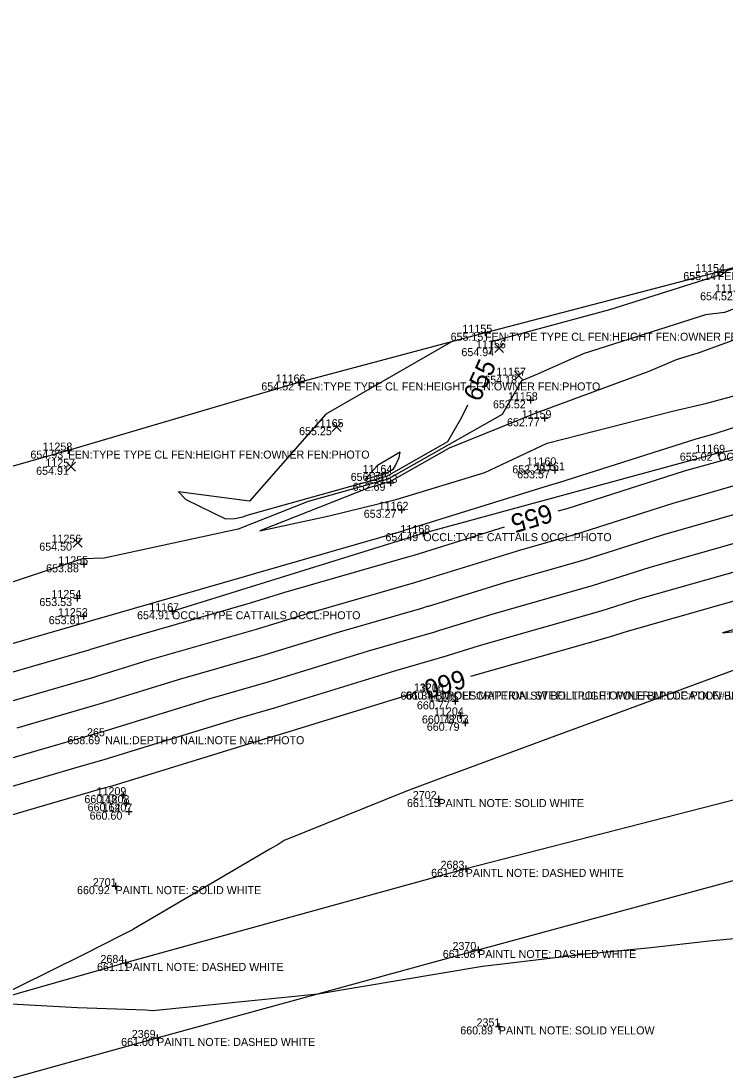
# Model space of a CAD drawing. Extents: x 2129350 to 2137777, y 657588 to 659885.
# Drawn here: x 2130064.8 to 2130170.4, y 657889 to 658046.3 of the extents above; entities that cross this region are included whole.
import ezdxf

# ---------------------------------------------------------------- set-up
doc = ezdxf.new("R2010")
doc.units = 0
for name, color, linetype in [('DT_X_Contour_Major', 7, 'Continuous'), ('DT_X_Contour_Minor', 7, 'Continuous'), ('DT_X_TIN_Hull', 7, 'Continuous'), ('PV_X_COP', 7, 'Continuous'), ('SV_X_Occupation_Line', 7, 'Continuous'), ('SV_X_Random_Point', 7, 'Continuous'), ('SV_X_Shot_Marker', 7, 'Continuous'), ('SV_X_Text_Comment', 7, 'Continuous'), ('SV_X_Text_Elevation', 7, 'Continuous'), ('SV_X_Text_Name', 7, 'Continuous')]:
    doc.layers.add(name, color=color, linetype=linetype)

msp = doc.modelspace()

# ---------------------------------------------------------------- linework, layer by layer
at = {"layer": 'DT_X_Contour_Major'}
for points in [[(2130135.26, 657996.37), (2130135.53, 657998.3), (2130153.1, 658003), (2130169.13, 658008.07), (2130169.76, 658008.15), (2130170.68, 658008.86), (2130207.13, 658019.25)], [(2130145.36, 657972.83), (2130146.73, 657973.21), (2130164.33, 657978.81), (2130170.25, 657980.49), (2130170.87, 657980.67), (2130178.19, 657983.07), (2130184.13, 657984.71), (2130202.48, 657988.72), (2130206.5, 657989.34), (2130213.65, 657991.31), (2130224.32, 657996.57), (2130224.46, 657996.61), (2130241.1, 658000.69)], [(2130129.37, 657998.2), (2130110.5, 657987.31), (2130099.06, 657974.3), (2130088.39, 657975.7), (2130089.52, 657974.52), (2130095.46, 657971.63), (2130096.84, 657971.67), (2130098.08, 657971.94), (2130098.72, 657972.19), (2130119.66, 657978.02), (2130119.68, 657978.03), (2130128.83, 657983.21), (2130130.91, 657986.87), (2130131.81, 657988.74)], [(2130228.35, 657975.26), (2130228.33, 657975.26), (2130226.38, 657974.3), (2130205.36, 657968.48), (2130204.63, 657968.37), (2130201.34, 657967.65), (2130180.5, 657961.87), (2130179.2, 657961.44), (2130176.95, 657960.8), (2130155.69, 657954.76), (2130153.02, 657953.91), (2130132.19, 657948.01)], [(2130041.36, 657942.26), (2130051.69, 657945.25), (2130055.75, 657946.43), (2130075.01, 657952), (2130075.27, 657952.08), (2130079.61, 657953.41), (2130099.21, 657959.04), (2130104.19, 657960.57), (2130123.15, 657966.03), (2130123.55, 657966.15), (2130123.75, 657966.21), (2130137.31, 657970.42)], [(2130124.14, 657945.59), (2130103.64, 657939.28), (2130101.6, 657938.7), (2130079.71, 657931.95), (2130078.4, 657931.57), (2130076.87, 657931.13), (2130054.42, 657924.58), (2130053.07, 657924.19), (2130030.38, 657917.57), (2130030.36, 657917.56), (2130030.36, 657917.56), (2130029.26, 657917.28), (2130028.32, 657916.99)]]:
    msp.add_lwpolyline(points, dxfattribs=at)
at = {"layer": 'DT_X_Contour_Minor'}
for points in [[(2130173.21, 658003.68), (2130170.31, 658002.6), (2130167.47, 658002.21), (2130149.09, 657996.4), (2130142.25, 657993.33), (2130139.84, 657992.31), (2130136.98, 657987.29), (2130119.9, 657977.61), (2130119.85, 657977.59), (2130107.84, 657974.25), (2130097.34, 657970.1), (2130077.27, 657965.74), (2130073.99, 657965.64), (2130053.45, 657958.82)], [(2130175.12, 657999.7), (2130166.23, 657996.41), (2130165.8, 657996.35), (2130163.04, 657995.48), (2130162.01, 657995.02), (2130158.96, 657993.72), (2130142.54, 657987.69), (2130142.51, 657987.68), (2130129.03, 657982.24), (2130120.12, 657977.19), (2130120.05, 657977.16), (2130116.96, 657976.3), (2130100.61, 657969.84), (2130111, 657972.08), (2130121, 657974.54), (2130121.03, 657974.55), (2130121.19, 657974.59), (2130134.34, 657978.58), (2130143.72, 657982.96), (2130143.73, 657982.96), (2130162.5, 657987.79), (2130167.67, 657988.97), (2130177.09, 657991.53)], [(2130051.53, 657949.49), (2130074.34, 657956.09), (2130074.38, 657956.1), (2130075.21, 657956.35), (2130098.33, 657962.99), (2130099.99, 657963.5), (2130122.27, 657969.91), (2130122.44, 657969.97), (2130122.67, 657970.03), (2130143.89, 657976.62), (2130145.47, 657977.07), (2130166.06, 657983.62), (2130168.9, 657984.43), (2130169.21, 657984.52), (2130177.73, 657987.3)], [(2130119.46, 657978.45), (2130120.68, 657979.14), (2130120.96, 657979.63), (2130121.53, 657980.81), (2130121.64, 657981.62), (2130118.24, 657979.63), (2130116.42, 657977.6), (2130119.46, 657978.45), (2130119.46, 657978.45)], [(2130059.97, 657943.37), (2130075.69, 657947.91), (2130076.16, 657948.05), (2130084.01, 657950.47), (2130100.1, 657955.09), (2130108.39, 657957.64), (2130124.03, 657962.14), (2130124.67, 657962.34), (2130124.82, 657962.38), (2130139.74, 657967.01), (2130147.99, 657969.35), (2130162.6, 657974), (2130171.59, 657976.56)], [(2130064.2, 657940.31), (2130076.37, 657943.83), (2130077.05, 657944.03), (2130088.4, 657947.53), (2130100.98, 657951.14), (2130112.58, 657954.71), (2130124.92, 657958.26), (2130125.78, 657958.52), (2130125.9, 657958.56), (2130137.66, 657962.21), (2130149.24, 657965.49), (2130160.87, 657969.19), (2130172.93, 657972.62)], [(2130053.33, 657932.85), (2130068.42, 657937.25), (2130077.05, 657939.74), (2130077.93, 657940), (2130092.8, 657944.58), (2130101.87, 657947.19), (2130116.78, 657951.77), (2130125.8, 657954.37), (2130126.89, 657954.7), (2130126.98, 657954.73), (2130135.59, 657957.41), (2130150.5, 657961.63), (2130159.15, 657964.38), (2130174.27, 657968.68)], [(2130175.61, 657964.74), (2130157.42, 657959.57), (2130151.76, 657957.77), (2130133.51, 657952.6), (2130128.06, 657950.91), (2130128, 657950.89), (2130126.68, 657950.48), (2130120.98, 657948.84), (2130102.75, 657943.23), (2130097.2, 657941.64), (2130078.82, 657935.98), (2130077.72, 657935.66), (2130072.65, 657934.19), (2130053.87, 657928.71)], [(2130178.29, 657956.87), (2130170.03, 657954.52), (2130173.15, 657954.87)], [(2130180.24, 657952.07), (2130164.98, 657946.44), (2130154.81, 657942.7), (2130144.05, 657938.73), (2130129.45, 657933.36), (2130128.71, 657933.09), (2130128.6, 657933.05), (2130122.61, 657930.82), (2130104.28, 657923.38), (2130103.38, 657922.81), (2130102.1, 657922.11), (2130081.64, 657910.1), (2130081.59, 657910.07), (2130079.93, 657909.23), (2130074.09, 657906.26), (2130059.6, 657899.1), (2130073.25, 657898.34), (2130083.44, 657898), (2130084.56, 657897.91), (2130109.32, 657900.4), (2130109.32, 657900.4), (2130109.32, 657900.4), (2130134.02, 657904.56), (2130134.05, 657904.56), (2130149.13, 657906.36), (2130159.24, 657907.35), (2130167.99, 657908.35), (2130184.51, 657909.89)]]:
    msp.add_lwpolyline(points, dxfattribs=at)
at = {"layer": 'DT_X_TIN_Hull'}
msp.add_lwpolyline([(2130245.51, 658030.02), (2130169.29, 658008.63), (2130134.39, 657999.54), (2130106.47, 657992.08), (2130071.87, 657981.87), (2130012.21, 657964.92), (2129966.74, 657952.64), (2129918.6, 657939.53), (2129870.14, 657926.57), (2129855.49, 657922.41), (2129844.49, 657920.37), (2129839.1, 657899.07), (2129833.96, 657888.24), (2129831.53, 657881.88), (2129820.99, 657877.99), (2129803, 657870.9), (2129789.34, 657849.46), (2129788.09, 657848.81), (2129788.13, 657848.34), (2129789.97, 657847.16), (2129789.65, 657836.99), (2129741.65, 657823.5), (2129717.53, 657816.91), (2129695.67, 657810.93)], dxfattribs=at)
at = {"layer": 'PV_X_COP'}
for points in [[(2130756.8, 658090.85), (2130709.64, 658077.1), (2130660.65, 658064.17), (2130611.76, 658050.53), (2130564.1, 658038.01), (2130516.21, 658024.74), (2130467.7, 658011.29), (2130419.56, 657997.56), (2130371.3, 657984.1), (2130323.4, 657971.71), (2130275.02, 657958.65), (2130226.86, 657945.08), (2130178.24, 657931.16), (2130131.49, 657919.16), (2130080.47, 657905.05), (2130033.67, 657891.71)], [(2130037.09, 657880.45), (2130085.21, 657893.8), (2130133.36, 657906.99), (2130181.98, 657920.22), (2130229.94, 657933.91), (2130277.86, 657946.56), (2130326.08, 657959.87), (2130374.09, 657973.32), (2130422.71, 657986.65), (2130470.82, 658000.08), (2130519.45, 658012.91), (2130567.41, 658026.23), (2130615.61, 658039.6), (2130663.49, 658052.2), (2130712.28, 658065.72), (2130760.53, 658079.19)]]:
    msp.add_lwpolyline(points, dxfattribs=at)
at = {"layer": 'SV_X_Occupation_Line'}
msp.add_lwpolyline([(2130087.44, 657957.79), (2130125.12, 657969.49), (2130169.35, 657981.55), (2130211.47, 657989.69), (2130262.21, 658002.55), (2130300.39, 658019.48), (2130344.82, 658026.09), (2130388.98, 658037.78), (2130435.6, 658050.49), (2130554.92, 658087.06), (2130644.25, 658113.16), (2130752.81, 658143.9), (2130803.09, 658157.94), (2130847.96, 658175.12), (2130903.78, 658194.81)], dxfattribs=at)
at = {"layer": 'SV_X_Random_Point'}
for p, q in [((2130135.85, 657996.56), (2130137.18, 657997.89)), ((2130135.85, 657997.89), (2130137.18, 657996.56)), ((2130138.8, 657992.43), (2130140.13, 657993.76)), ((2130138.8, 657993.76), (2130140.13, 657992.43)), ((2130111.46, 657984.72), (2130112.79, 657986.05)), ((2130111.46, 657986.05), (2130112.79, 657984.72)), ((2130071.63, 657978.78), (2130072.96, 657980.11)), ((2130071.63, 657980.11), (2130072.96, 657978.78)), ((2130072.62, 657967.39), (2130073.95, 657968.73)), ((2130072.62, 657968.73), (2130073.95, 657967.39))]:
    msp.add_line(p, q, dxfattribs=at)
at = {"layer": 'SV_X_Shot_Marker'}
for p, q in [((2130169.29, 658009.13), (2130169.29, 658008.13)), ((2130168.79, 658008.63), (2130169.79, 658008.63)), ((2130169.29, 658008.63), (2130169.29, 658008.63)), ((2130133.89, 657999.54), (2130134.89, 657999.54)), ((2130134.39, 658000.04), (2130134.39, 657999.04)), ((2130134.39, 657999.54), (2130134.39, 657999.54)), ((2130105.98, 657992.08), (2130106.98, 657992.08)), ((2130106.48, 657992.58), (2130106.48, 657991.58)), ((2130106.48, 657992.08), (2130106.48, 657992.08)), ((2130140.73, 657989.41), (2130141.73, 657989.41)), ((2130141.23, 657989.91), (2130141.23, 657988.91)), ((2130141.23, 657989.41), (2130141.23, 657989.41)), ((2130143.29, 657987.22), (2130143.29, 657986.22)), ((2130142.79, 657986.72), (2130143.79, 657986.72)), ((2130143.29, 657986.72), (2130143.29, 657986.72)), ((2130071.87, 657982.37), (2130071.87, 657981.37)), ((2130071.37, 657981.87), (2130072.37, 657981.87)), ((2130071.87, 657981.87), (2130071.87, 657981.87)), ((2130168.85, 657981.55), (2130169.85, 657981.55)), ((2130169.35, 657982.05), (2130169.35, 657981.05)), ((2130169.35, 657981.55), (2130169.35, 657981.55)), ((2130119.43, 657979.02), (2130119.43, 657978.02)), ((2130143.63, 657979.65), (2130144.63, 657979.65)), ((2130144.13, 657980.15), (2130144.13, 657979.15)), ((2130144.13, 657979.65), (2130144.13, 657979.65)), ((2130144.87, 657979.41), (2130144.87, 657978.41)), ((2130118.93, 657978.52), (2130119.93, 657978.52)), ((2130119.43, 657978.52), (2130119.43, 657978.52)), ((2130120.19, 657977.54), (2130120.19, 657976.54)), ((2130144.37, 657978.91), (2130145.37, 657978.91)), ((2130144.87, 657978.91), (2130144.87, 657978.91)), ((2130119.69, 657977.04), (2130120.69, 657977.04)), ((2130120.19, 657977.04), (2130120.19, 657977.04)), ((2130121.34, 657972.99), (2130122.34, 657972.99)), ((2130121.84, 657973.49), (2130121.84, 657972.49)), ((2130121.84, 657972.99), (2130121.84, 657972.99)), ((2130124.62, 657969.49), (2130125.62, 657969.49)), ((2130125.12, 657969.99), (2130125.12, 657968.99)), ((2130125.12, 657969.49), (2130125.12, 657969.49)), ((2130073.73, 657964.82), (2130074.73, 657964.82)), ((2130074.23, 657965.32), (2130074.23, 657964.32)), ((2130074.23, 657964.82), (2130074.23, 657964.82)), ((2130073.2, 657960.26), (2130073.2, 657959.26)), ((2130072.7, 657959.76), (2130073.7, 657959.76)), ((2130073.2, 657959.76), (2130073.2, 657959.76)), ((2130073.68, 657957.04), (2130074.68, 657957.04)), ((2130074.18, 657957.54), (2130074.18, 657956.54)), ((2130074.18, 657957.04), (2130074.18, 657957.04)), ((2130086.94, 657957.79), (2130087.94, 657957.79)), ((2130087.44, 657958.29), (2130087.44, 657957.29)), ((2130087.44, 657957.79), (2130087.44, 657957.79)), ((2130129.92, 657944.78), (2130129.92, 657943.78)), ((2130129.42, 657944.28), (2130130.42, 657944.28)), ((2130129.92, 657944.28), (2130129.92, 657944.28)), ((2130130.18, 657942.16), (2130131.18, 657942.16)), ((2130130.68, 657942.66), (2130130.68, 657941.66)), ((2130130.68, 657942.16), (2130130.68, 657942.16)), ((2130131.42, 657941.56), (2130131.42, 657940.56)), ((2130130.92, 657941.06), (2130131.92, 657941.06)), ((2130131.42, 657941.06), (2130131.42, 657941.06)), ((2130079.59, 657930.2), (2130080.59, 657930.2)), ((2130080.09, 657930.7), (2130080.09, 657929.7)), ((2130080.09, 657930.2), (2130080.09, 657930.2)), ((2130080.07, 657928.98), (2130081.07, 657928.98)), ((2130080.57, 657929.48), (2130080.57, 657928.48)), ((2130080.57, 657928.98), (2130080.57, 657928.98)), ((2130126.9, 657929.62), (2130127.9, 657929.62)), ((2130127.4, 657930.12), (2130127.4, 657929.12)), ((2130127.4, 657929.62), (2130127.4, 657929.62)), ((2130080.48, 657927.73), (2130081.48, 657927.73)), ((2130080.98, 657928.23), (2130080.98, 657927.23)), ((2130080.98, 657927.73), (2130080.98, 657927.73)), ((2130130.99, 657919.16), (2130131.99, 657919.16)), ((2130131.49, 657919.66), (2130131.49, 657918.66)), ((2130131.49, 657919.16), (2130131.49, 657919.16)), ((2130078.47, 657916.55), (2130079.47, 657916.55)), ((2130078.97, 657917.05), (2130078.97, 657916.05)), ((2130078.97, 657916.55), (2130078.97, 657916.55)), ((2130132.86, 657906.99), (2130133.86, 657906.99)), ((2130133.36, 657907.49), (2130133.36, 657906.49)), ((2130133.36, 657906.99), (2130133.36, 657906.99)), ((2130079.97, 657905.05), (2130080.97, 657905.05)), ((2130080.47, 657905.55), (2130080.47, 657904.55)), ((2130080.47, 657905.05), (2130080.47, 657905.05)), ((2130136.46, 657896.03), (2130136.46, 657895.03)), ((2130085.21, 657894.3), (2130085.21, 657893.3)), ((2130135.96, 657895.53), (2130136.96, 657895.53)), ((2130136.46, 657895.53), (2130136.46, 657895.53)), ((2130084.71, 657893.8), (2130085.71, 657893.8)), ((2130085.21, 657893.8), (2130085.21, 657893.8))]:
    msp.add_line(p, q, dxfattribs=at)

# ---------------------------------------------------------------- texts
at = {"layer": 'DT_X_Contour_Major'}
for s, rotation, p in [('655', 65.6517, (2130133.57, 657989.03)), ('655', 196.6286, (2130144, 657973.93)), ('660', 196.7113, (2130130.98, 657949.09))]:
    msp.add_text(s, height=2.8, rotation=rotation, dxfattribs=at).set_placement(p)
at = {"layer": 'SV_X_Text_Comment'}
for s, p in [('FEN:TYPE TYPE CL FEN:HEIGHT FEN:OWNER FEN:PHOTO', (2130169.29, 658007.43)), ('FEN:TYPE TYPE CL FEN:HEIGHT FEN:OWNER FEN:PHOTO', (2130134.39, 657998.34)), ('FEN:TYPE TYPE CL FEN:HEIGHT FEN:OWNER FEN:PHOTO', (2130106.48, 657990.89)), ('FEN:TYPE TYPE CL FEN:HEIGHT FEN:OWNER FEN:PHOTO', (2130071.87, 657980.67)), ('OCCL:TYPE CATTAILS OCCL:PHOTO', (2130169.35, 657980.35)), ('OCCL:TYPE CATTAILS OCCL:PHOTO', (2130125.12, 657968.29)), ('OCCL:TYPE CATTAILS OCCL:PHOTO', (2130087.44, 657956.58)), ('BM:DESCRIPTION SW BOLT LIGHT POLE BM:LOCATION BM:NOTE BM:PHOTO', (2130126.91, 657944.53)), ('LPOLE:MATERIAL STEEL LPOLE:OWNER LPOLE:POLE# LPOLE:PHOTO', (2130127.77, 657944.55)), ('NAIL:DEPTH 0 NAIL:NOTE NAIL:PHOTO', (2130077.42, 657937.84)), ('PAINTL NOTE: SOLID WHITE', (2130127.4, 657928.42)), ('PAINTL NOTE: DASHED WHITE', (2130131.49, 657917.95)), ('PAINTL NOTE: SOLID WHITE', (2130078.97, 657915.36)), ('PAINTL NOTE: DASHED WHITE', (2130133.36, 657905.79)), ('PAINTL NOTE: DASHED WHITE', (2130080.47, 657903.85)), ('PAINTL NOTE: SOLID YELLOW', (2130136.46, 657894.33)), ('PAINTL NOTE: DASHED WHITE', (2130085.21, 657892.6))]:
    msp.add_text(s, height=1.2, dxfattribs=at).set_placement(p)
at = {"layer": 'SV_X_Text_Elevation'}
for s, p in [('655.14', (2130164.13, 658007.43)), ('654.52', (2130166.65, 658004.41)), ('655.15', (2130129.23, 657998.34)), ('654.94', (2130130.85, 657996.03)), ('654.18', (2130134.28, 657991.9)), ('654.52', (2130100.84, 657990.89)), ('653.52', (2130135.58, 657988.21)), ('655.25', (2130106.5, 657984.18)), ('652.77', (2130137.69, 657985.52)), ('654.93', (2130066.2, 657980.67)), ('655.02', (2130163.61, 657980.35)), ('654.91', (2130067.06, 657978.24)), ('653.28', (2130138.48, 657978.45)), ('653.57', (2130139.21, 657977.71)), ('656.19', (2130114.24, 657977.32)), ('652.69', (2130114.54, 657975.84)), ('653.27', (2130116.2, 657971.79)), ('654.49', (2130119.45, 657968.29)), ('654.50', (2130067.53, 657966.86)), ('653.88', (2130068.56, 657963.62)), ('653.53', (2130067.54, 657958.56)), ('653.81', (2130068.95, 657955.84)), ('654.91', (2130082.2, 657956.58)), ('661.34', (2130121.71, 657944.53)), ('660.17', (2130122.47, 657944.55)), ('660.77', (2130124.17, 657943.08)), ('660.78', (2130124.92, 657940.96)), ('660.79', (2130125.66, 657939.86)), ('658.69', (2130071.75, 657937.84)), ('660.48', (2130074.3, 657929)), ('660.64', (2130074.78, 657927.79)), ('661.15', (2130122.68, 657928.42)), ('660.60', (2130075.08, 657926.53)), ('661.28', (2130126.31, 657917.95)), ('660.92', (2130073.19, 657915.36)), ('661.08', (2130128.05, 657905.79)), ('661.11', (2130076.19, 657903.85)), ('660.89', (2130130.68, 657894.33)), ('661.00', (2130079.81, 657892.6))]:
    msp.add_text(s, height=1.2, dxfattribs=at).set_placement(p)
at = {"layer": 'SV_X_Text_Name'}
for s, p in [('11154', (2130165.91, 658008.63)), ('11153', (2130168.9, 658005.61)), ('11155', (2130131, 657999.54)), ('11156', (2130133.05, 657997.22)), ('11166', (2130102.99, 657992.08)), ('11157', (2130136.07, 657993.1)), ('11158', (2130137.83, 657989.41)), ('11159', (2130139.89, 657986.72)), ('11165', (2130108.71, 657985.38)), ('11258', (2130068.02, 657981.87)), ('11169', (2130165.93, 657981.55)), ('11257', (2130068.45, 657979.44)), ('11160', (2130140.62, 657979.65)), ('11164', (2130116.03, 657978.52)), ('11161', (2130141.9, 657978.91)), ('11163', (2130116.79, 657977.04)), ('11162', (2130118.44, 657972.99)), ('11168', (2130121.7, 657969.49)), ('11256', (2130069.37, 657968.06)), ('11255', (2130070.39, 657964.82)), ('11254', (2130069.36, 657959.76)), ('11167', (2130084.03, 657957.79)), ('11253', (2130070.33, 657957.04)), ('11206', (2130123.73, 657945.75)), ('321', (2130124.61, 657945.73)), ('11205', (2130125.97, 657944.28)), ('11204', (2130126.74, 657942.16)), ('11203', (2130127.46, 657941.06)), ('265', (2130074.69, 657939.04)), ('11209', (2130076.13, 657930.2)), ('11208', (2130076.6, 657928.98)), ('2702', (2130123.56, 657929.62)), ('11207', (2130077.02, 657927.73)), ('2683', (2130127.72, 657919.16)), ('2701', (2130075.56, 657916.55)), ('2370', (2130129.51, 657906.99)), ('2684', (2130076.71, 657905.05)), ('2351', (2130133.12, 657895.53)), ('2369', (2130081.41, 657893.8))]:
    msp.add_text(s, height=1.2, dxfattribs=at).set_placement(p)

doc.saveas('drawing.dxf')
